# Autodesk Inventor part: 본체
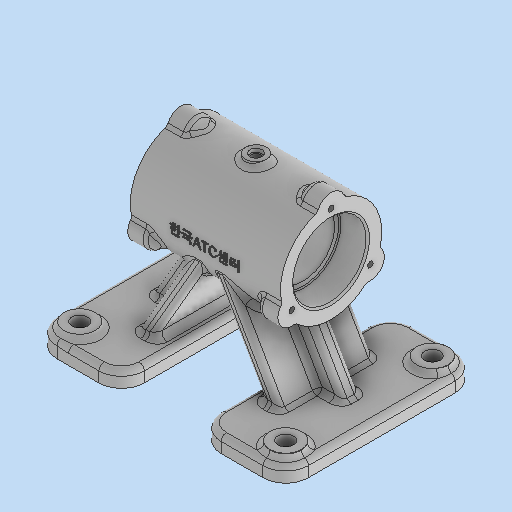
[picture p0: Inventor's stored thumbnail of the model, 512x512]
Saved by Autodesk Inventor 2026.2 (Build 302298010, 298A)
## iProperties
Created: 2026-04
Part Number: 본체
Material: 일반
Document SubType Name: Modeling
Designer: PC-2-03
Density: 1 g/cm^3
Appearance: 기본값
Author: PC-2-03
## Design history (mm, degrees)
sketch "스케치1"
  geometry: L1 (-72, 55)-(72, 55); L2 (72, 55)-(72, -55); L3 (72, -55)-(-72, -55); L4 (-72, -55)-(-72, 55); 3 further points
  constraints: 8 end point, 2 midpoint, 2 parallel, 1 horizontal, 1 horizontal alignment, 1 perpendicular, 1 vertical alignment
  dimensions: "d0" = 144 distance between parallel lines of L4 L2; "d1" = 110 distance of L1.end L2.end
extrude "돌출1" new body sketch "스케치1" distance "d2" = 9; taper "d3" = 0 deg
sketch "스케치2"
  geometry: L1 (72, 55)-(-72, 55) reference; L2 (-22, -55)-(22, -55); L3 (22, -55)-(22, 55); L4 (22, 55)-(-22, 55); L5 (-22, 55)-(-22, -55); L6 (-22, -55)-(22, 55); L7 (22, -55)-(-22, 55); 2 further points
  constraints: 12 end point, 2 midpoint, 2 parallel, 1 horizontal, 1 perpendicular, 1 point on line
  dimensions: "d4" = 44 distance between parallel lines of L3 L5
extrude "돌출2" cut sketch "스케치2" extent not by distance; stored distance "d5" = 0; taper "d6" = 0 deg
sketch "스케치3"
  geometry: L1 (-55, 0)-(55, 0) reference; L2 (55, 0)-(55, 9) reference; C1 r 29 at (0, 72); 1 further point
  constraints: 1 centre point
  dimensions: "d7" = 58 diameter of C1; "d8" = 72 distance from line of L1 C1.centre; "d9" = 55 distance from line of C1.centre L2
extrude "돌출3" join sketch "스케치3" stored distance "d10" = 86; taper "d11" = 0 deg
sketch "스케치4"
  geometry: L1 (22, 9)-(72, 9) reference; L2 (43, 43)-(-43, 43) reference; L3 (0, 64.426)-(-32, 9); L4 (-72, 9)-(-22, 9) reference; L5 (-4.865, 72)-(-41.238, 9); L6 (4.865, 72)-(41.238, 9); L7 (0, 43)-(0, 21.006); L8 (32, 9)-(-1.549, 67.108); L9 (6.618, 75.888)-(-0.31, 79.888); L10 (43, 43)-(43, 101) reference; L11 (43, 72)-(4.865, 72); L12 (-4.865, 72)-(-43, 72); L13 (4.865, 72)-(-4.865, 72); 3 further points
  constraints: 18 end point, 7 point on line, 3 horizontal, 2 midpoint, 2 parallel, 1 perpendicular, 1 vertical
  dimensions: "d13" = 8 distance from line of L3 point (-33.577, 22.269); "d14" = 30 deg angle of L7 L3 (= 0.5 x d12); "d15" = 10 distance of L4.end L3.end; "d18" = 60 deg angle of L3 L8; "d19" = 8 distance between parallel lines of L8 L6; "d20" = 10 distance of L1.start L8.start; "d21" = 81.85451 distance of L9.end L5.end
extrude "돌출4" join sketch "스케치4" stored distance "d22" = 54; taper "d23" = 0 deg
sketch "스케치5" dims "d156" = 52
  geometry: A1 r 29 centre (0, 0) between (-27.942, -7.761) and (-27.942, 7.761) reference; A2 r 8 centre (-26, 0) between (-27.942, 7.761) and (-27.942, -7.761); 2 further points
  constraints: 4 point on circle, 2 horizontal alignment, 1 centre point, 3 other
  dimensions: "d157" = 8 radius of A2
extrude "돌출5" join sketch "스케치5" distance "d25" = 10; taper "d26" = 0 deg
sketch "스케치6" dims "d161" = 52
  geometry: A1 r 29 centre (0, 0) between (27.942, 7.761) and (27.942, -7.761) reference; A2 r 8 centre (26, 0) between (27.942, -7.761) and (27.942, 7.761); 2 further points
  constraints: 4 point on circle, 2 horizontal alignment, 1 centre point, 3 other
  dimensions: "d162" = 8 radius of A2
extrude "돌출6" join sketch "스케치6" distance "d31" = 10; taper "d32" = 0 deg
node "작업 평면1"
sketch "스케치7"
  geometry: C1 r 6 at (0, 0); 1 further point
  constraints: 1 centre point, 1 coincident
  dimensions: "d37" = 12 diameter of C1
extrude "돌출7" join sketch "스케치7" stored distance "d38" = 10; taper "d39" = 0 deg
node "작업 평면2"
sketch "스케치8"
  geometry: C1 r 6 at (0, 0); 1 further point
  constraints: 1 centre point, 1 coincident
  dimensions: "d41" = 12 diameter of C1
extrude "돌출8" join sketch "스케치8" stored distance "d42" = 10; taper "d43" = 0 deg
sketch "스케치11"
  geometry: C1 r 6 at (0, 0) reference; 2 further points
  constraints: 1 coincident
hole "구멍3" sketch "스케치11" at (0, 0) diameter "d58" = 5.1881; stored, may be unused: countersink angle "d62" = 90 deg, drill point angle "d64" = 0 deg; dims "d59" = 12, "d60" = 7, "d61" = 2, "d63" = 102.4
sketch "스케치12"
  geometry: C1 r 6 at (0, 0) reference; 2 further points
  constraints: 1 coincident
hole "구멍4" sketch "스케치12" at (0, 0) diameter "d65" = 7; stored, may be unused: countersink angle "d69" = 90 deg, drill point angle "d71" = 0 deg; dims "d66" = 12, "d67" = 7, "d68" = 2, "d70" = 2
sketch "스케치13"
  geometry: L1 (-72, 9)-(-22, 9) reference; L2 (-55.094, 9)-(-44.568, 27.231); L3 (-10.975, 61.417)-(-41.238, 9) reference; 1 further point
  constraints: 2 end point, 1 parallel, 1 point on line
  dimensions: "d72" = 12 distance between parallel lines of L3 L2
feature "리브1" sketch "스케치13" dims "d73" = 1, "d74" = 10, "d75" = 0, "d76" = 0, "d77" = 1, "d78" = 1
sketch "스케치14"
  geometry: L1 (22, 9)-(72, 9) reference; L2 (55.094, 9)-(49.718, 18.312); L3 (41.238, 9)-(10.975, 61.417) reference; 1 further point
  constraints: 2 end point, 1 parallel, 1 point on line
  dimensions: "d79" = 12 distance between parallel lines of L2 L3
feature "리브2" sketch "스케치14" dims "d80" = 1, "d81" = 10, "d82" = 0, "d83" = 0, "d84" = 1, "d85" = 1
sketch "스케치15"
  geometry: L1 (43, 98)-(25, 98); L2 (33, 106)-(33, 99.942) reference; L3 (25, 98)-(33, 106); L4 (43, 64.75)-(43, 99.942) reference; L5 (33, 106)-(33, 98); 3 further points
  constraints: 6 end point, 1 horizontal, 1 point on line, 1 vertical
  dimensions: "d163" = 45 deg angle of L3 L1; "d164" = 8 distance from line of L2.start L1
revolve "회전1" sketch "스케치15" stored, may be unused: angle "d87" = 360 deg
sketch "스케치16"
  geometry: L1 (-43, 106)-(-33, 106) reference; L2 (-33, 99.942)-(-33, 106) reference; L3 (-25, 98)-(-33, 106); L4 (-25, 98)-(-43, 98); L5 (-33, 106)-(-33, 98); 4 further points
  constraints: 6 end point, 2 point on line, 1 horizontal, 1 midpoint
  dimensions: "d159" = 16 diameter of L1 L4; "d160" = 45 deg angle of L4 L3
revolve "회전2" sketch "스케치16" stored, may be unused: angle "d92" = 360 deg
fillet "모깎기1" dims "d96" = 13
sketch "스케치17"
  geometry: C1 r 9 at (59, 42); A1 r 13 centre (59, 42) between (72, 42) and (59, 55) reference; 1 further point
  constraints: 1 centre point, 1 concentric
  dimensions: "d97" = 18 diameter of C1
extrude "돌출9" join sketch "스케치17" distance "d98" = 3; taper "d99" = 0 deg
sketch "스케치18"
  geometry: C1 r 9 at (0, 0) reference; 2 further points
  constraints: 1 coincident
hole "구멍5" sketch "스케치18" at (0, 0) diameter "d100" = 9; stored, may be unused: countersink angle "d104" = 90 deg, drill point angle "d106" = 0 deg; dims "d101" = 6, "d102" = 4, "d103" = 2, "d105" = 2
sketch "스케치19" dims "d113" = 52
  geometry: A1 r 29 centre (-72, 0) between (-99.942, -7.761) and (-64.75, -28.079) reference; A2 r 29 centre (-72, 0) between (-99.942, -7.761) and (-64.75, -28.079) reference; 7 further points
  constraints: 2 horizontal alignment, 1 coincident, 3 other
hole "구멍6" sketch "스케치19" at (-98, 0) diameter "d114" = 3.242; stored, may be unused: countersink angle "d118" = 90 deg, drill point angle "d120" = 118 deg; dims "d115" = 8, "d116" = 4, "d117" = 2, "d119" = 10
sketch "스케치9"
  geometry: A1 r 29 centre (-72, 0) between (-99.942, -7.761) and (-64.75, -28.079) reference; 4 further points
  constraints: 1 coincident
hole "구멍1" sketch "스케치9" at (-72, 0) diameter "d44" = 36; stored, may be unused: countersink angle "d48" = 90 deg, drill point angle "d50" = 0 deg; dims "d45" = 8, "d46" = 42, "d47" = 16, "d49" = 10
sketch "스케치10"
  geometry: C1 r 18 at (72, 0) reference; 2 further points
  constraints: 1 coincident
hole "구멍2" sketch "스케치10" at (72, 0) diameter "d51" = 42; stored, may be unused: countersink angle "d55" = 90 deg, drill point angle "d57" = 0 deg; dims "d52" = 6, "d53" = 42, "d54" = 16, "d56" = 16
sketch "스케치20" dims "d124" = 52
  geometry: A1 r 29 centre (72, 0) between (99.942, 7.761) and (64.75, 28.079) reference; 5 further points
  constraints: 2 horizontal alignment, 3 other
hole "구멍7" sketch "스케치20" at (98, 0) diameter "d125" = 3.242; stored, may be unused: countersink angle "d129" = 90 deg, drill point angle "d131" = 118 deg; dims "d126" = 8, "d127" = 4, "d128" = 2, "d130" = 10
fillet "모깎기2" dims "d135" = 3
fillet "모깎기3" dims "d136" = 3
fillet "모깎기15" dims "d170" = 3
fillet "모깎기4" dims "d137" = 3
fillet "모깎기7" dims "d140" = 3
chamfer "모따기1" distance "d143" = 1; stored, may be unused: second distance "d144" = 2, angle "d145" = 45 deg
fillet "모깎기10" dims "d146" = 3
fillet "모깎기11" dims "d147" = 0.6
node "작업 평면3"
sketch "스케치21"
  geometry: L1 (20, 5)-(-20, 5); L2 (-20, 5)-(-20, -5); L3 (-20, -5)-(20, -5); L4 (20, -5)-(20, 5); L5 (-20, 0)-(20, 0); L6 (0, -5)-(0, 5); L7 (-35, 72)-(-59, 72) reference; L8 (-43, 7.25)-(-43, -27.942) reference; 1 further point
  constraints: 4 end point, 4 midpoint, 2 other
  dimensions: "d149" = 10 distance between parallel lines of L1 L3; "d150" = 40 distance of L2.end L3.end; "d151" = 72 distance between parallel lines of L7 L5; "d152" = 43 distance between parallel lines of L8 L6
feature "엠보싱1" sketch "스케치21" dims "d153" = 0.5, "d154" = 0
fillet "모깎기12" dims "d155" = 3
fillet "모깎기13" dims "d165" = 3
fillet "모깎기14" dims "d166" = 3
node "솔리드1"
pattern_circular "원형 패턴1" dims angle "d28" = 360 deg
pattern_circular "원형 패턴2" dims angle "d34" = 360 deg
pattern_circular "원형 패턴3" dims angle "d89" = 360 deg
pattern_circular "원형 패턴4" dims angle "d94" = 360 deg
pattern_linear "직사각형 패턴1" dims "d112" = 84, "d169" = 118
pattern_circular "원형 패턴5" dims angle "d122" = 360 deg
pattern_circular "원형 패턴6" dims angle "d133" = 360 deg
feature "A9D066F2-1C7D-4E18-AEED-F7BC21143FA4" dims "d65" = 7, "d66" = 12, "d67" = 7, "d68" = 2, "d69" = 90 deg, "d70" = 2, "d71" = 0
other parameters: "d12" = 60 deg, "d36" = 104
